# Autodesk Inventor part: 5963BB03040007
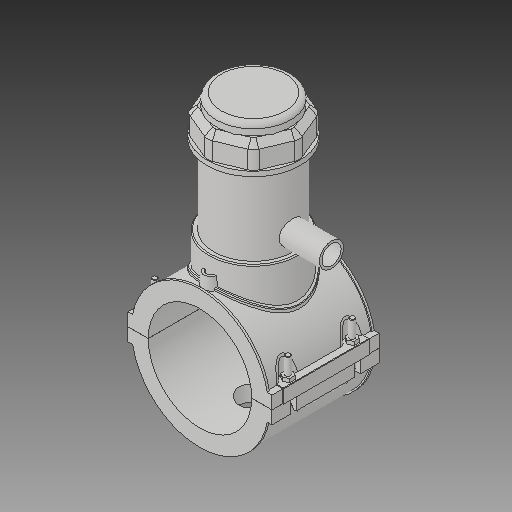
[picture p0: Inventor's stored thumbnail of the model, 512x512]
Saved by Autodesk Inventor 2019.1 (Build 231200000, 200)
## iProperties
Created: 2017-07
Part Number: 5963BB03040007
Material: Generic
Description: PLASSON TAPPING SADDLE 4''IPS x 1 3/4''IPS
Document SubType Name: Modeling
Designer: KIM
Mass: 1712.7 g
Surface Area: 2671.49 cm^2
Volume: 1712.7 cm^3
Density: 1 g/cm^3
Appearance: Default
Author: KIM
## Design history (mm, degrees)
derived "5963B.ipt"
feature "Solid1::5963B.ipt"
feature "Solid2::5963B.ipt"
feature "Solid4::5963B.ipt"
feature "Solid5::5963B.ipt"
tag "TaggingFeature1"
body "Solid1"
body "Solid2"
other parameters: "d0" = 114.1, "d2" = 159.004, "d3" = 28.525, "d4" = 118.11, "d5" = 0, "d6" = 0.1, "d8" = 0, "d19" = 6, "d20" = 6, "d21" = 70.866, "d23" = 0, "d24" = 35.433, "d26" = 0, "d29" = 3, "d30" = 38.03333, "d31" = 6, "d32" = 0, "d33" = 0, "d34" = 0.6, "d40" = 77.1316, "d41" = 102.69, "d43" = 0, "d45" = 0, "d47" = 145.031, "d70" = 15, "d72" = 0, "d73" = 6, "d75" = 5, "d76" = 0, "d77" = 5.705, "d78" = 87.05, "d79" = 15, "d80" = 47.244, "d82" = 5 deg, "d84" = 4, "d85" = 14, "d86" = 0, "d87" = 3, "d88" = 0, "d89" = 1, "d90" = 1, "d91" = 94.488, "d92" = 0, "d93" = 0.5, "d94" = 60.05263, "d96" = 151.2966, "d97" = 2.3622, "d98" = 0, "d102" = 1.141, "d120" = 140 deg, "d121" = 24.228, "d122" = 20 deg, "d123" = 296.66, "d124" = 88.998, "d126" = 0, "d143" = 117.523, "d145" = 26.33077, "d149" = 1.7115, "d150" = 28.96385, "d153" = 118.11, "d154" = 0, "d156" = 74.165, "d157" = 160 deg, "d159" = 6.846, "d161" = 1.7115, "d162" = 70.866, "d163" = 0, "d164" = 57.05, "d167" = 11.41, "d168" = 72.3561, "d170" = 3.2805, "d172" = 0, "d173" = 1, "d175" = 57.05, "d176" = 20 deg, "d177" = 7.987, "d178" = 34.23, "d180" = 0, "d183" = 13.692, "d184" = 6.3896, "d185" = 38.38575, "d186" = 38.38575, "d187" = 74.165, "d188" = 10.269, "d189" = 7.987, "d190" = 0, "d191" = 111.2475, "d193" = 6.1236, "d194" = 4.13385, "d195" = 90 deg, "d197" = 0, "d199" = 0, "d200" = 17.115, "d202" = 0, "d203" = 177.038, "d204" = 97.5555, "d205" = 71.883, "d206" = 87.2865, "d207" = 132.7785, "d208" = 138.08964, "d209" = 164.64534, "d210" = 88.3134, "d211" = 102.69, "d212" = 82.152, "d213" = 46.5516, "d216" = 0, "d217" = 11.41, "d218" = 5.705, "d219" = 1.141, "d222" = 114.1, "d224" = 0, "d230" = 6.846, "d233" = 6, "d236" = 79.502, "d237" = 35.433, "d238" = 6.02433, "d240" = 35.433, "d241" = 35.433, "d242" = 35.433, "d243" = 6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
